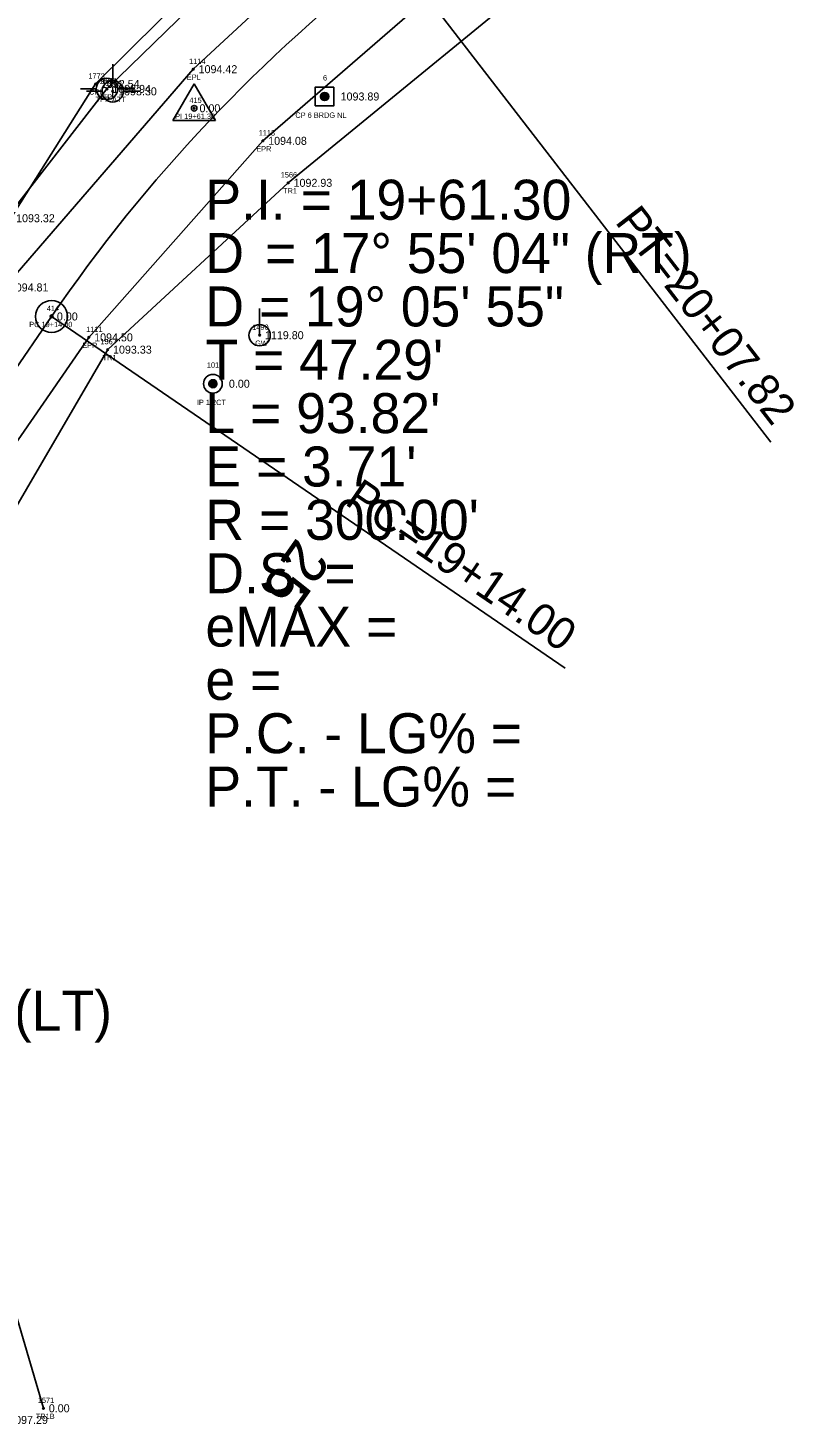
# Model space of a CAD drawing. Extents: x 1539151 to 1541799, y 1198646 to 1201165.
# Drawn here: x 1540218.7 to 1540362.7, y 1199378.3 to 1199640 of the extents above; entities that cross this region are included whole.
import ezdxf

# ---------------------------------------------------------------- set-up
doc = ezdxf.new("R2010")
doc.units = 0
for name, color, linetype in [('RD_EX_DV_Prop_txCode', 7, 'Continuous'), ('RD_EX_DV_PropPin', 7, 'Continuous'), ('RD_EX_H2O', 7, 'Continuous'), ('RD_EX_H2O_txCode', 7, 'Continuous'), ('RD_EX_Road', 7, 'Continuous'), ('RD_EX_Road_txCode', 7, 'Continuous'), ('RD_EX_TX_Driveway_ELEV', 7, 'Continuous'), ('RD_EX_TX_DV_Prop_ELEV', 7, 'Continuous'), ('RD_EX_TX_H2O_ELEV', 7, 'Continuous'), ('RD_EX_TX_Road_ELEV', 7, 'Continuous'), ('RD_EX_TX_UT_ELEV', 7, 'Continuous'), ('RD_EX_TX_VEG_ELEV', 7, 'Continuous'), ('RD_EX_UT', 7, 'Continuous'), ('RD_EX_UT_txCode', 7, 'Continuous'), ('RD_EX_VEG', 7, 'Continuous'), ('RD_EX_VEG_txCode', 7, 'Continuous'), ('RD_HC_Cl', 7, 'Continuous'), ('RD_HC_Data', 7, 'Continuous'), ('RD_HC_Survey', 7, 'Continuous'), ('RD_HC_Survey_ELEV', 7, 'Continuous'), ('RD_HC_Survey_txCode', 7, 'Continuous'), ('RD_HC_TX_Sta50', 7, 'Continuous'), ('RD_HC_txCode', 7, 'Continuous'), ('RD_SMD_Locator', 7, 'Continuous')]:
    doc.layers.add(name, color=color, linetype=linetype)

msp = doc.modelspace()

# ---------------------------------------------------------------- linework, layer by layer
at = {"layer": 'RD_EX_DV_PropPin'}
for p, q in [((1540252.66, 1199573.06), (1540252.66, 1199573.45)), ((1540252.7, 1199572.96), (1540252.7, 1199573.55)), ((1540252.73, 1199572.89), (1540252.73, 1199573.63)), ((1540252.77, 1199572.83), (1540252.77, 1199573.68)), ((1540252.8, 1199572.78), (1540252.8, 1199573.73)), ((1540252.84, 1199572.74), (1540252.84, 1199573.77)), ((1540252.87, 1199572.71), (1540252.87, 1199573.81)), ((1540252.91, 1199572.67), (1540252.91, 1199573.84)), ((1540252.94, 1199572.65), (1540252.94, 1199573.87)), ((1540252.98, 1199572.62), (1540252.98, 1199573.89)), ((1540253.01, 1199572.6), (1540253.01, 1199573.91)), ((1540253.05, 1199572.58), (1540253.05, 1199573.93)), ((1540253.08, 1199572.56), (1540253.08, 1199573.95)), ((1540253.12, 1199572.55), (1540253.12, 1199573.96)), ((1540253.15, 1199572.54), (1540253.15, 1199573.98)), ((1540253.19, 1199572.53), (1540253.19, 1199573.99)), ((1540253.22, 1199572.52), (1540253.22, 1199574)), ((1540253.26, 1199572.51), (1540253.26, 1199574)), ((1540253.29, 1199572.5), (1540253.29, 1199574.01)), ((1540253.33, 1199572.5), (1540253.33, 1199574.01)), ((1540253.36, 1199572.5), (1540253.36, 1199574.02)), ((1540253.4, 1199572.5), (1540253.4, 1199574.02)), ((1540253.43, 1199572.5), (1540253.43, 1199574.02)), ((1540253.47, 1199572.5), (1540253.47, 1199574.01)), ((1540253.5, 1199572.5), (1540253.5, 1199574.01)), ((1540253.54, 1199572.51), (1540253.54, 1199574)), ((1540253.57, 1199572.52), (1540253.57, 1199574)), ((1540253.61, 1199572.53), (1540253.61, 1199573.99)), ((1540253.64, 1199572.54), (1540253.64, 1199573.98)), ((1540253.68, 1199572.55), (1540253.68, 1199573.96)), ((1540253.71, 1199572.56), (1540253.71, 1199573.95)), ((1540253.75, 1199572.58), (1540253.75, 1199573.93)), ((1540253.78, 1199572.6), (1540253.78, 1199573.91)), ((1540253.82, 1199572.62), (1540253.82, 1199573.89)), ((1540253.85, 1199572.65), (1540253.85, 1199573.87)), ((1540253.89, 1199572.67), (1540253.89, 1199573.84)), ((1540253.92, 1199572.71), (1540253.92, 1199573.81)), ((1540253.96, 1199572.74), (1540253.96, 1199573.77)), ((1540253.99, 1199572.78), (1540253.99, 1199573.73)), ((1540254.03, 1199572.83), (1540254.03, 1199573.68)), ((1540254.06, 1199572.89), (1540254.06, 1199573.63)), ((1540254.1, 1199572.96), (1540254.1, 1199573.55)), ((1540254.13, 1199573.06), (1540254.13, 1199573.45))]:
    msp.add_line(p, q, dxfattribs=at)
for radius in [1.75, 0.761]:
    msp.add_circle((1540253.4, 1199573.26), radius, dxfattribs=at)
at = {"layer": 'RD_EX_H2O'}
msp.add_lwpolyline([(1540745.24, 1200145.69), (1540714.12, 1200111.24), (1540686.99, 1200083.09), (1540635.75, 1200037.11), (1540573.3, 1199996.4), (1540513.92, 1199967.81), (1540469.14, 1199939.84), (1540434.54, 1199909.73), (1540407.32, 1199874.45), (1540364.13, 1199846.32), (1540277.43, 1199809.38), (1540253.91, 1199804.21), (1540226.93, 1199780.46), (1540229.17, 1199750.37), (1540235.89, 1199732.91), (1540246.94, 1199713.51), (1540253.28, 1199693.01), (1540254.24, 1199673.46), (1540249.65, 1199647.58), (1540231.41, 1199629.45), (1540215.51, 1199604.28), (1540200.09, 1199580.59)], dxfattribs=at)
at = {"layer": 'RD_EX_Road'}
for points in [[(1540156.86, 1199508.27), (1540186.51, 1199551.73), (1540214.32, 1199591.31), (1540249.72, 1199632.22), (1540286.8, 1199666.61), (1540324.36, 1199693.31), (1540344.92, 1199710.43), (1540367.33, 1199727.77), (1540402.7, 1199760.37), (1540437.37, 1199795.58), (1540455.74, 1199815.52), (1540466.15, 1199827.23), (1540503.86, 1199868.5), (1540538.69, 1199906.78), (1540571.44, 1199944.18), (1540603.42, 1199982.61), (1540638.15, 1200019.15), (1540672.1, 1200056.68), (1540705.32, 1200094.04), (1540739.01, 1200131.56)], [(1540170.57, 1199494.63), (1540181.23, 1199508.28), (1540202.24, 1199541.54), (1540230.14, 1199581.95), (1540262.76, 1199618.79), (1540299.65, 1199650.78), (1540338.78, 1199681.63), (1540378.45, 1199712.68), (1540416.67, 1199747.15), (1540451.68, 1199783.64), (1540485.11, 1199820.19), (1540518.57, 1199856.95), (1540552.63, 1199894.89), (1540585.47, 1199932.32), (1540619.12, 1199969.78), (1540652.74, 1200007.33), (1540685.87, 1200044.5), (1540718.68, 1200081.33), (1540762.24, 1200130.19)]]:
    msp.add_lwpolyline(points, dxfattribs=at)
at = {"layer": 'RD_EX_UT'}
for p, q in [((1540234.63, 1199633.13), (1540234.63, 1199630.06)), ((1540228.61, 1199628.54), (1540231.54, 1199628.54)), ((1540229.7, 1199628.07), (1540232.63, 1199628.07)), ((1540235.54, 1199628.54), (1540238.61, 1199628.54)), ((1540236.63, 1199628.07), (1540239.7, 1199628.07)), ((1540262.16, 1199582.36), (1540262.16, 1199587.36))]:
    msp.add_line(p, q, dxfattribs=at)
for centre in [(1540233.54, 1199628.53), (1540234.63, 1199628.06), (1540262.16, 1199582.36)]:
    msp.add_circle(centre, 2, dxfattribs=at)
at = {"layer": 'RD_EX_VEG'}
for points in [[(1540712.01, 1200109.09), (1540564.8, 1199952.12), (1540511.25, 1199924.62), (1540488.55, 1199863.43), (1540394.02, 1199755.91), (1540277.54, 1199671.42), (1540233.54, 1199628.53), (1540200.18, 1199585.62), (1540155.93, 1199516.08), (1540069.9, 1199571.55)], [(1540836.37, 1200082.45), (1540794.45, 1200101.71), (1540758.65, 1200106.39), (1540697.29, 1200033.83), (1540560.39, 1199886.45), (1540422.51, 1199739.87), (1540382.08, 1199704.72), (1540267.52, 1199610.92), (1540233.68, 1199579.65), (1540209.33, 1199537.96), (1540187.75, 1199496.51), (1540221.64, 1199381.22)]]:
    msp.add_lwpolyline(points, dxfattribs=at)
at = {"layer": 'RD_HC_Cl'}
msp.add_line((1540187.83, 1199534.28), (1540223.16, 1199585.87), dxfattribs=at)
msp.add_arc((1540470.67, 1199416.35), 300, 127.6745, 145.5923, dxfattribs=at)
at = {"layer": 'RD_HC_Data'}
for p, q in [((1540287.32, 1199653.79), (1540357.97, 1199562.31)), ((1540245.92, 1199622.6), (1540249.89, 1199629.48)), ((1540249.89, 1199629.48), (1540253.86, 1199622.6)), ((1540245.92, 1199622.6), (1540253.86, 1199622.6)), ((1540223.16, 1199585.87), (1540319.44, 1199519.93))]:
    msp.add_line(p, q, dxfattribs=at)
for centre, radius in [((1540249.89, 1199624.89), 0.529), ((1540223.16, 1199585.87), 3), ((1540223.16, 1199585.87), 0.282)]:
    msp.add_circle(centre, radius, dxfattribs=at)
at = {"layer": 'RD_HC_Survey'}
for p, q in [((1540273.59, 1199626.92), (1540273.59, 1199627.28)), ((1540273.62, 1199626.84), (1540273.62, 1199627.36)), ((1540273.64, 1199626.78), (1540273.64, 1199627.42)), ((1540273.67, 1199626.73), (1540273.67, 1199627.47)), ((1540273.69, 1199626.69), (1540273.69, 1199627.52)), ((1540273.72, 1199626.65), (1540273.72, 1199627.55)), ((1540273.74, 1199626.62), (1540273.74, 1199627.58)), ((1540273.77, 1199626.59), (1540273.77, 1199627.61)), ((1540273.79, 1199626.56), (1540273.79, 1199627.64)), ((1540273.82, 1199626.54), (1540273.82, 1199627.66)), ((1540273.84, 1199626.52), (1540273.84, 1199627.69)), ((1540273.87, 1199626.5), (1540273.87, 1199627.71)), ((1540273.89, 1199626.48), (1540273.89, 1199627.73)), ((1540273.92, 1199626.46), (1540273.92, 1199627.74)), ((1540273.94, 1199626.45), (1540273.94, 1199627.76)), ((1540273.97, 1199626.43), (1540273.97, 1199627.77)), ((1540273.99, 1199626.42), (1540273.99, 1199627.79)), ((1540274.02, 1199626.41), (1540274.02, 1199627.8)), ((1540274.04, 1199626.4), (1540274.04, 1199627.81)), ((1540274.07, 1199626.39), (1540274.07, 1199627.82)), ((1540274.09, 1199626.38), (1540274.09, 1199627.83)), ((1540274.11, 1199626.37), (1540274.11, 1199627.84)), ((1540274.14, 1199626.36), (1540274.14, 1199627.84)), ((1540274.16, 1199626.35), (1540274.16, 1199627.85)), ((1540274.19, 1199626.35), (1540274.19, 1199627.86)), ((1540274.21, 1199626.34), (1540274.21, 1199627.86)), ((1540274.24, 1199626.34), (1540274.24, 1199627.86)), ((1540274.26, 1199626.34), (1540274.26, 1199627.87)), ((1540274.29, 1199626.34), (1540274.29, 1199627.87)), ((1540274.31, 1199626.33), (1540274.31, 1199627.87)), ((1540274.34, 1199626.33), (1540274.34, 1199627.87)), ((1540274.36, 1199626.33), (1540274.36, 1199627.87)), ((1540274.39, 1199626.33), (1540274.39, 1199627.87)), ((1540274.41, 1199626.34), (1540274.41, 1199627.87)), ((1540274.44, 1199626.34), (1540274.44, 1199627.87)), ((1540274.46, 1199626.34), (1540274.46, 1199627.86)), ((1540274.49, 1199626.35), (1540274.49, 1199627.86)), ((1540274.51, 1199626.35), (1540274.51, 1199627.85)), ((1540274.54, 1199626.36), (1540274.54, 1199627.85)), ((1540274.56, 1199626.36), (1540274.56, 1199627.84)), ((1540274.58, 1199626.37), (1540274.58, 1199627.83)), ((1540274.61, 1199626.38), (1540274.61, 1199627.82)), ((1540274.63, 1199626.39), (1540274.63, 1199627.81)), ((1540274.66, 1199626.4), (1540274.66, 1199627.8)), ((1540274.68, 1199626.41), (1540274.68, 1199627.79)), ((1540274.71, 1199626.43), (1540274.71, 1199627.78)), ((1540274.73, 1199626.44), (1540274.73, 1199627.77)), ((1540274.76, 1199626.45), (1540274.76, 1199627.75)), ((1540274.78, 1199626.47), (1540274.78, 1199627.73)), ((1540274.81, 1199626.49), (1540274.81, 1199627.72)), ((1540274.83, 1199626.51), (1540274.83, 1199627.7)), ((1540274.86, 1199626.53), (1540274.86, 1199627.68)), ((1540274.88, 1199626.55), (1540274.88, 1199627.65)), ((1540274.91, 1199626.58), (1540274.91, 1199627.63)), ((1540274.93, 1199626.61), (1540274.93, 1199627.6)), ((1540274.96, 1199626.64), (1540274.96, 1199627.57)), ((1540274.98, 1199626.67), (1540274.98, 1199627.53)), ((1540275.01, 1199626.71), (1540275.01, 1199627.49)), ((1540275.03, 1199626.76), (1540275.03, 1199627.45)), ((1540275.06, 1199626.81), (1540275.06, 1199627.39)), ((1540275.08, 1199626.88), (1540275.08, 1199627.33)), ((1540275.1, 1199626.99), (1540275.1, 1199627.21))]:
    msp.add_line(p, q, dxfattribs=at)
msp.add_lwpolyline([(1540276.09, 1199628.85), (1540272.59, 1199628.85), (1540272.59, 1199625.35), (1540276.09, 1199625.35)], close=True, dxfattribs=at)
msp.add_circle((1540274.34, 1199627.1), 0.769, dxfattribs=at)
at = {"layer": 'RD_SMD_Locator'}
for centre in [(1540249.72, 1199632.22), (1540231.41, 1199629.45), (1540233.54, 1199628.53), (1540233.54, 1199628.53), (1540234.63, 1199628.06), (1540274.34, 1199627.1), (1540249.89, 1199624.89), (1540262.76, 1199618.79), (1540267.52, 1199610.92), (1540223.16, 1199585.87), (1540230.14, 1199581.95), (1540262.16, 1199582.36), (1540233.68, 1199579.65), (1540253.4, 1199573.26), (1540221.64, 1199381.22)]:
    msp.add_circle(centre, 0.15, dxfattribs=at)

# ---------------------------------------------------------------- texts
at = {"layer": 'RD_EX_DV_Prop_txCode'}
for s, p in [('1016', (1540252.27, 1199576.26)), ('IP 1/2CT', (1540250.39, 1199569.26))]:
    msp.add_text(s, height=1, dxfattribs=at).set_placement(p)
at = {"layer": 'RD_EX_H2O_txCode'}
for s, p in [('1773', (1540230.06, 1199630.45)), ('CRL', (1540230.18, 1199627.45))]:
    msp.add_text(s, height=1, dxfattribs=at).set_placement(p)
at = {"layer": 'RD_EX_Road_txCode'}
for s, p in [('1114', (1540248.94, 1199633.22)), ('EPL', (1540248.51, 1199630.22)), ('1113', (1540261.98, 1199619.79)), ('EPR', (1540261.53, 1199616.79)), ('1111', (1540229.64, 1199582.95)), ('EPR', (1540228.91, 1199579.95))]:
    msp.add_text(s, height=1, dxfattribs=at).set_placement(p)
at = {"layer": 'RD_EX_TX_Driveway_ELEV'}
msp.add_text('1097.29', height=1.5, dxfattribs=at).set_placement((1540215.21, 1199378.28))
at = {"layer": 'RD_EX_TX_DV_Prop_ELEV'}
msp.add_text('0.00', height=1.5, dxfattribs=at).set_placement((1540256.4, 1199572.51))
at = {"layer": 'RD_EX_TX_H2O_ELEV'}
for s, p in [('1092.54', (1540232.41, 1199628.7)), ('1093.32', (1540216.51, 1199603.53))]:
    msp.add_text(s, height=1.5, dxfattribs=at).set_placement(p)
at = {"layer": 'RD_EX_TX_Road_ELEV'}
for s, p in [('1094.42', (1540250.72, 1199631.47)), ('1094.08', (1540263.76, 1199618.04)), ('1094.81', (1540215.32, 1199590.56)), ('1094.50', (1540231.14, 1199581.2))]:
    msp.add_text(s, height=1.5, dxfattribs=at).set_placement(p)
at = {"layer": 'RD_EX_TX_UT_ELEV'}
for s, p in [('1092.94', (1540234.54, 1199627.78)), ('1093.30', (1540235.63, 1199627.31)), ('1119.80', (1540263.16, 1199581.61))]:
    msp.add_text(s, height=1.5, dxfattribs=at).set_placement(p)
at = {"layer": 'RD_EX_TX_VEG_ELEV'}
for s, p in [('1092.94', (1540234.54, 1199627.78)), ('1092.93', (1540268.52, 1199610.17)), ('1093.33', (1540234.68, 1199578.9)), ('0.00', (1540222.64, 1199380.47))]:
    msp.add_text(s, height=1.5, dxfattribs=at).set_placement(p)
at = {"layer": 'RD_EX_UT'}
msp.add_text('T', height=2, dxfattribs=at).set_placement((1540233.78, 1199627.01))
at = {"layer": 'RD_EX_UT_txCode'}
for s, p in [('1680', (1540232.13, 1199629.53)), ('1679', (1540233.26, 1199629.06)), ('TPP ATT', (1540231.42, 1199626.06)), ('TP', (1540232.74, 1199626.53)), ('1490', (1540260.77, 1199583.36)), ('GW', (1540261.31, 1199580.36))]:
    msp.add_text(s, height=1, dxfattribs=at).set_placement(p)
at = {"layer": 'RD_EX_VEG_txCode'}
for s, p in [('1681', (1540232.45, 1199629.53)), ('TL', (1540232.76, 1199626.53)), ('1566', (1540266.12, 1199611.92)), ('TR1', (1540266.56, 1199608.92)), ('1567', (1540232.31, 1199580.65)), ('TR1', (1540232.72, 1199577.65)), ('1571', (1540220.58, 1199382.22)), ('TR1B', (1540220.21, 1199379.22))]:
    msp.add_text(s, height=1, dxfattribs=at).set_placement(p)
at = {"layer": 'RD_HC_Data'}
for s, p in [('P.I. = 19+61.30', (1540252, 1199604)), ('D', (1540252, 1199594)), ('    = 17%%d 55\' 04" (RT)', (1540252, 1199594)), ('D = 19%%d 05\' 55"', (1540252, 1199584)), ("T = 47.29'", (1540252, 1199574)), ("L = 93.82'", (1540252, 1199564)), ("E = 3.71'", (1540252, 1199554)), ("R = 300.00'", (1540252, 1199544)), ('D.S. = ', (1540252, 1199534)), ('eMAX = ', (1540252, 1199524)), ('e = ', (1540252, 1199514)), ('P.C. - LG% = ', (1540252, 1199504)), ('P.T. - LG% = ', (1540252, 1199494)), ('    = 16%%d 14\' 53" (LT)', (1540145, 1199452))]:
    msp.add_text(s, height=7.5, dxfattribs=at).set_placement(p)
for s, rotation, p in [('PT=20+07.82', 307.6745, (1540328.63, 1199603.57)), ('PC=19+14.00', 325.5923, (1540277.92, 1199550.79))]:
    msp.add_text(s, height=6, rotation=rotation, dxfattribs=at).set_placement(p)
at = {"layer": 'RD_HC_Survey_ELEV'}
for s, p in [('1093.89', (1540277.34, 1199626.35)), ('0.00', (1540250.89, 1199624.14)), ('0.00', (1540224.16, 1199585.12))]:
    msp.add_text(s, height=1.5, dxfattribs=at).set_placement(p)
at = {"layer": 'RD_HC_Survey_txCode'}
for s, p in [('6', (1540274.04, 1199630.1)), ('CP 6 BRDG NL', (1540268.86, 1199623.1))]:
    msp.add_text(s, height=1, dxfattribs=at).set_placement(p)
at = {"layer": 'RD_HC_TX_Sta50'}
msp.add_text('25', height=8, rotation=234.7394, dxfattribs=at).set_placement((1540269.18, 1199544.62))
at = {"layer": 'RD_HC_txCode'}
for s, p in [('415', (1540248.99, 1199625.89)), ('PI 19+61.30', (1540246.33, 1199622.89)), ('414', (1540222.26, 1199586.87)), ('PC 19+14.00', (1540218.97, 1199583.87))]:
    msp.add_text(s, height=1, dxfattribs=at).set_placement(p)

doc.saveas('drawing.dxf')
